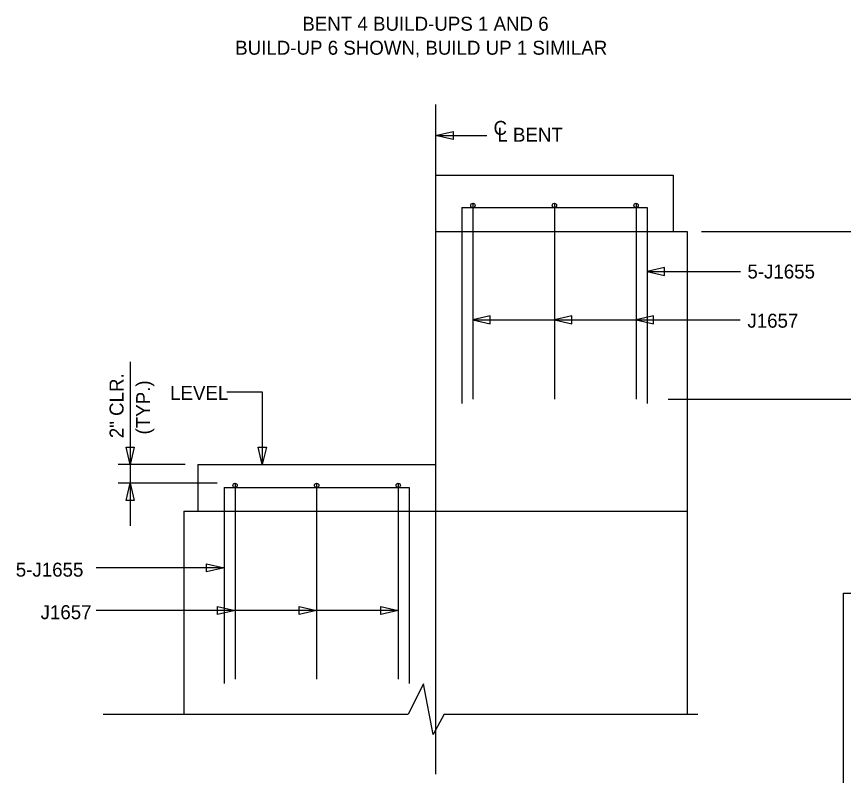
# Model space of a CAD drawing. Extents: x 1970675.2 to 1970711.3, y 796145.2 to 796167.2.
# Drawn here: x 1970697.93 to 1970705.32, y 796149.4 to 796156.17 of the extents above; entities that cross this region are included whole.
import ezdxf

# ---------------------------------------------------------------- set-up
doc = ezdxf.new("R2010")
doc.units = 0
for name, color, linetype in [('BR_AUTO DIMENSION', 7, 'Continuous'), ('BR_BORDER LINES', 7, 'Continuous'), ('BR_CENTER LINES', 7, 'Continuous'), ('BR_CONCRETE', 7, 'Continuous'), ('BR_REBAR', 7, 'Continuous'), ('Default', 7, 'Continuous')]:
    doc.layers.add(name, color=color, linetype=linetype)

msp = doc.modelspace()

# ---------------------------------------------------------------- linework, layer by layer
at = {"layer": 'BR_AUTO DIMENSION'}
for p, q in [((1970701.6734, 796155.112), (1970702.1328, 796155.112)), ((1970704.0511, 796154.2557), (1970705.6747, 796154.2557)), ((1970703.5641, 796153.8978), (1970704.3978, 796153.8978)), ((1970702.0068, 796153.4645), (1970704.3952, 796153.4645)), ((1970702.736, 796153.4645), (1970702.8161, 796153.4645)), ((1970703.736, 796153.4645), (1970703.8161, 796153.4645)), ((1970698.9447, 796153.0903), (1970698.9447, 796151.6253)), ((1970699.8085, 796152.8236), (1970700.1253, 796152.8236)), ((1970700.1253, 796152.8236), (1970700.1253, 796152.1734)), ((1970703.753, 796152.7557), (1970705.6747, 796152.7557)), ((1970699.4344, 796152.1734), (1970698.8356, 796152.1734)), ((1970699.7223, 796152.0067), (1970698.8356, 796152.0067)), ((1970699.7828, 796151.2499), (1970698.6413, 796151.2499)), ((1970701.3401, 796150.8701), (1970698.6413, 796150.8701)), ((1970700.6109, 796150.8701), (1970700.5308, 796150.8701))]:
    msp.add_line(p, q, dxfattribs=at)
for points in [[(1970701.8294, 796155.076), (1970701.6734, 796155.112), (1970701.8294, 796155.148)], [(1970703.7201, 796153.9338), (1970703.5641, 796153.8978), (1970703.7201, 796153.8618)], [(1970702.1628, 796153.5005), (1970702.0068, 796153.4645), (1970702.1628, 796153.4285)], [(1970702.892, 796153.5005), (1970702.736, 796153.4645), (1970702.892, 796153.4285)], [(1970703.6212, 796153.5005), (1970703.4652, 796153.4645), (1970703.6212, 796153.4285)], [(1970698.9807, 796152.3294), (1970698.9447, 796152.1734), (1970698.9087, 796152.3294)], [(1970700.1613, 796152.3294), (1970700.1253, 796152.1734), (1970700.0893, 796152.3294)], [(1970698.9087, 796151.8507), (1970698.9447, 796152.0067), (1970698.9807, 796151.8507)], [(1970699.6268, 796151.2859), (1970699.7828, 796151.2499), (1970699.6268, 796151.2139)], [(1970699.7257, 796150.9061), (1970699.8817, 796150.8701), (1970699.7257, 796150.8341)], [(1970700.4549, 796150.9061), (1970700.6109, 796150.8701), (1970700.4549, 796150.8341)], [(1970701.1841, 796150.9061), (1970701.3401, 796150.8701), (1970701.1841, 796150.8341)]]:
    msp.add_lwpolyline(points, close=True, dxfattribs=at)
at = {"layer": 'BR_BORDER LINES'}
for p, q in [((1970705.3189, 796145.7463), (1970705.3189, 796151.0229)), ((1970705.3189, 796151.0229), (1970710.7358, 796151.0229))]:
    msp.add_line(p, q, dxfattribs=at)
at = {"layer": 'BR_CENTER LINES'}
msp.add_line((1970701.6735, 796155.389), (1970701.6734, 796149.4064), dxfattribs=at)
at = {"layer": 'BR_CONCRETE'}
for p, q in [((1970701.6735, 796154.7567), (1970701.6734, 796151.7557)), ((1970701.6735, 796154.7567), (1970703.7985, 796154.7567)), ((1970703.7985, 796154.7567), (1970703.7985, 796154.2557)), ((1970701.6735, 796154.2557), (1970703.9235, 796154.2557)), ((1970703.9235, 796154.2557), (1970703.9234, 796151.7557)), ((1970699.5484, 796152.1734), (1970699.5484, 796151.7557)), ((1970699.5484, 796152.1734), (1970701.6734, 796152.1734)), ((1970699.4234, 796151.7557), (1970699.4234, 796149.9437)), ((1970699.4234, 796151.7557), (1970703.9234, 796151.7557)), ((1970703.9234, 796151.7557), (1970703.9234, 796149.9437))]:
    msp.add_line(p, q, dxfattribs=at)
at = {"layer": 'BR_REBAR'}
for p, q in [((1970701.9079, 796154.4677), (1970701.9079, 796152.7177)), ((1970701.9079, 796154.4677), (1970703.5641, 796154.4677)), ((1970702.0068, 796154.5067), (1970702.0068, 796152.7567)), ((1970702.736, 796154.5067), (1970702.736, 796152.7567)), ((1970703.4652, 796154.5067), (1970703.4652, 796152.7567)), ((1970703.5641, 796154.4677), (1970703.5641, 796152.7177)), ((1970699.8817, 796152.0067), (1970699.8817, 796150.2567)), ((1970700.6109, 796152.0067), (1970700.6109, 796150.2567)), ((1970701.3401, 796152.0067), (1970701.3401, 796150.2567)), ((1970699.7828, 796151.9677), (1970699.7828, 796150.2177)), ((1970699.7828, 796151.9677), (1970701.439, 796151.9677)), ((1970701.439, 796151.9677), (1970701.439, 796150.2177))]:
    msp.add_line(p, q, dxfattribs=at)
for centre in [(1970702.0068, 796154.4872), (1970702.736, 796154.4872), (1970703.4652, 796154.4872), (1970699.8817, 796151.9872), (1970700.6109, 796151.9872), (1970701.3401, 796151.9872)]:
    msp.add_circle(centre, 0.0195, dxfattribs=at)
at = {"layer": 'Default'}
for p, q in [((1970698.7035, 796149.9437), (1970701.4277, 796149.9437)), ((1970701.751, 796149.9437), (1970704.0181, 796149.9437))]:
    msp.add_line(p, q, dxfattribs=at)
msp.add_lwpolyline([(1970701.751, 796149.9437), (1970701.6519, 796149.761), (1970701.5668, 796150.2133), (1970701.4277, 796149.9437)], dxfattribs=at)

# ---------------------------------------------------------------- texts
at = {"layer": 'BR_AUTO DIMENSION'}
for s, height, p in [('BENT 4 BUILD-UPS 1 AND 6', 0.125002, (1970700.4828, 796156.0479)), ('BUILD-UP 6 SHOWN, BUILD UP 1 SIMILAR', 0.125002, (1970699.8828, 796155.8336)), ('5-J1655', 0.125, (1970704.4605, 796153.8348)), ('J1657', 0.125, (1970704.4605, 796153.3955)), ('5-J1655', 0.125, (1970697.9219, 796151.1717)), ('J1657', 0.125, (1970698.1435, 796150.7919))]:
    msp.add_text(s, height=height, dxfattribs=at).set_placement(p)
for s, rotation, p in [('C', 360, (1970702.1916, 796155.1174)), ('L BENT', 360, (1970702.2259, 796155.0569)), ('2" CLR.', 90, (1970698.885, 796152.4085)), ('(TYP.)', 90, (1970699.1225, 796152.4416)), ('LEVEL', 360, (1970699.3012, 796152.7506))]:
    msp.add_text(s, height=0.125, rotation=rotation, dxfattribs=at).set_placement(p)

doc.saveas('drawing.dxf')
